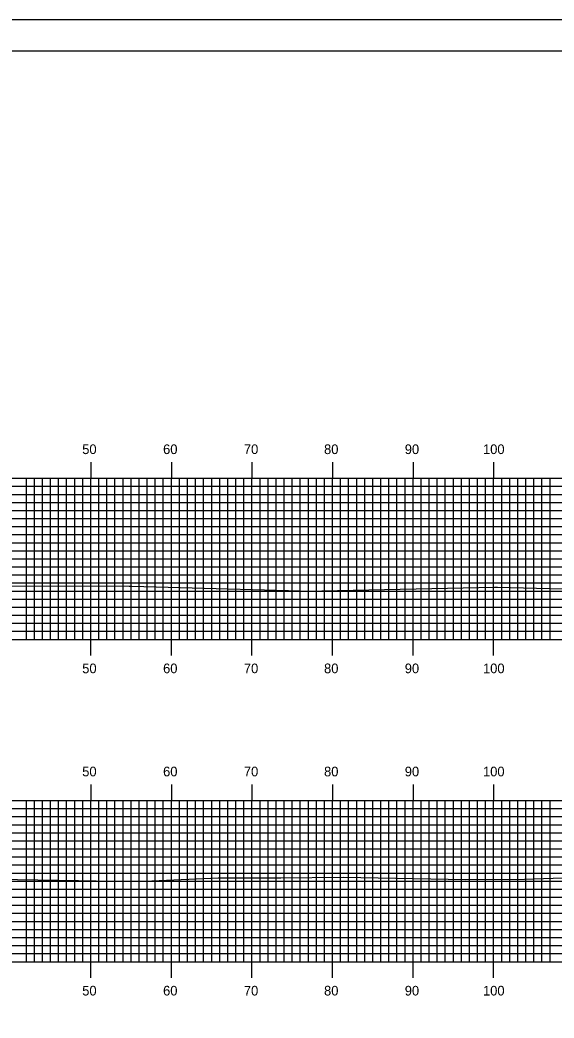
# Model space of a CAD drawing. Extents: x 1777925 to 1778268, y 442591 to 442811.
# Drawn here: x 1778132 to 1778198.3, y 442686.7 to 442810.5 of the extents above; entities that cross this region are included whole.
import ezdxf

# ---------------------------------------------------------------- set-up
doc = ezdxf.new("R2010")
doc.units = 0
for name, color, linetype in [('BORDER', 7, 'Continuous'), ('H_V ANNOTATION', 7, 'Continuous'), ('MAJOR', 7, 'Continuous'), ('MINOR', 7, 'Continuous'), ('PLOT BOUNDARY', 7, 'Continuous'), ('S_Roadway_Centerline', 7, 'Continuous')]:
    doc.layers.add(name, color=color, linetype=linetype)

msp = doc.modelspace()

# ---------------------------------------------------------------- linework, layer by layer
at = {"layer": 'BORDER'}
msp.add_lwpolyline([(1777941.19, 442596.67), (1778261.19, 442596.67), (1778261.19, 442806.67), (1777941.19, 442806.67)], close=True, dxfattribs=at)
at = {"layer": 'MAJOR'}
for p, q in [((1778140.79, 442755.67), (1778140.79, 442753.67)), ((1778150.79, 442755.67), (1778150.79, 442753.67)), ((1778160.79, 442755.67), (1778160.79, 442753.67)), ((1778170.79, 442755.67), (1778170.79, 442753.67)), ((1778180.79, 442755.67), (1778180.79, 442753.67)), ((1778190.79, 442755.67), (1778190.79, 442753.67)), ((1777950.79, 442753.67), (1778230.79, 442753.67)), ((1777950.79, 442753.67), (1778230.79, 442753.67)), ((1778140.79, 442733.67), (1778140.79, 442753.67)), ((1778150.79, 442733.67), (1778150.79, 442753.67)), ((1778160.79, 442733.67), (1778160.79, 442753.67)), ((1778170.79, 442733.67), (1778170.79, 442753.67)), ((1778180.79, 442733.67), (1778180.79, 442753.67)), ((1778190.79, 442733.67), (1778190.79, 442753.67)), ((1777950.79, 442748.67), (1778230.79, 442748.67)), ((1777950.79, 442743.67), (1778230.79, 442743.67)), ((1777950.79, 442738.67), (1778230.79, 442738.67)), ((1777950.79, 442733.67), (1778230.79, 442733.67)), ((1777950.79, 442733.67), (1778230.79, 442733.67)), ((1778140.79, 442731.66), (1778140.79, 442733.67)), ((1778150.79, 442731.66), (1778150.79, 442733.67)), ((1778160.79, 442731.66), (1778160.79, 442733.67)), ((1778170.79, 442731.66), (1778170.79, 442733.67)), ((1778180.79, 442731.66), (1778180.79, 442733.67)), ((1778190.79, 442731.66), (1778190.79, 442733.67)), ((1778140.79, 442715.67), (1778140.79, 442713.67)), ((1778150.79, 442715.67), (1778150.79, 442713.67)), ((1778160.79, 442715.67), (1778160.79, 442713.67)), ((1778170.79, 442715.67), (1778170.79, 442713.67)), ((1778180.79, 442715.67), (1778180.79, 442713.67)), ((1778190.79, 442715.67), (1778190.79, 442713.67)), ((1777950.79, 442713.67), (1778230.79, 442713.67)), ((1777950.79, 442713.67), (1778230.79, 442713.67)), ((1778140.79, 442693.67), (1778140.79, 442713.67)), ((1778150.79, 442693.67), (1778150.79, 442713.67)), ((1778160.79, 442693.67), (1778160.79, 442713.67)), ((1778170.79, 442693.67), (1778170.79, 442713.67)), ((1778180.79, 442693.67), (1778180.79, 442713.67)), ((1778190.79, 442693.67), (1778190.79, 442713.67)), ((1777950.79, 442708.67), (1778230.79, 442708.67)), ((1777950.79, 442703.67), (1778230.79, 442703.67)), ((1777950.79, 442698.67), (1778230.79, 442698.67)), ((1777950.79, 442693.67), (1778230.79, 442693.67)), ((1777950.79, 442693.67), (1778230.79, 442693.67)), ((1778140.79, 442691.66), (1778140.79, 442693.67)), ((1778150.79, 442691.66), (1778150.79, 442693.67)), ((1778160.79, 442691.66), (1778160.79, 442693.67)), ((1778170.79, 442691.66), (1778170.79, 442693.67)), ((1778180.79, 442691.66), (1778180.79, 442693.67)), ((1778190.79, 442691.66), (1778190.79, 442693.67))]:
    msp.add_line(p, q, dxfattribs=at)
at = {"layer": 'MINOR'}
for p, q in [((1778132.79, 442733.67), (1778132.79, 442753.67)), ((1778133.79, 442733.67), (1778133.79, 442753.67)), ((1778134.79, 442733.67), (1778134.79, 442753.67)), ((1778135.79, 442733.67), (1778135.79, 442753.67)), ((1778136.79, 442733.67), (1778136.79, 442753.67)), ((1778137.79, 442733.67), (1778137.79, 442753.67)), ((1778138.79, 442733.67), (1778138.79, 442753.67)), ((1778139.79, 442733.67), (1778139.79, 442753.67)), ((1778141.79, 442733.67), (1778141.79, 442753.67)), ((1778142.79, 442733.67), (1778142.79, 442753.67)), ((1778143.79, 442733.67), (1778143.79, 442753.67)), ((1778144.79, 442733.67), (1778144.79, 442753.67)), ((1778145.79, 442733.67), (1778145.79, 442753.67)), ((1778146.79, 442733.67), (1778146.79, 442753.67)), ((1778147.79, 442733.67), (1778147.79, 442753.67)), ((1778148.79, 442733.67), (1778148.79, 442753.67)), ((1778149.79, 442733.67), (1778149.79, 442753.67)), ((1778151.79, 442733.67), (1778151.79, 442753.67)), ((1778152.79, 442733.67), (1778152.79, 442753.67)), ((1778153.79, 442733.67), (1778153.79, 442753.67)), ((1778154.79, 442733.67), (1778154.79, 442753.67)), ((1778155.79, 442733.67), (1778155.79, 442753.67)), ((1778156.79, 442733.67), (1778156.79, 442753.67)), ((1778157.79, 442733.67), (1778157.79, 442753.67)), ((1778158.79, 442733.67), (1778158.79, 442753.67)), ((1778159.79, 442733.67), (1778159.79, 442753.67)), ((1778161.79, 442733.67), (1778161.79, 442753.67)), ((1778162.79, 442733.67), (1778162.79, 442753.67)), ((1778163.79, 442733.67), (1778163.79, 442753.67)), ((1778164.79, 442733.67), (1778164.79, 442753.67)), ((1778165.79, 442733.67), (1778165.79, 442753.67)), ((1778166.79, 442733.67), (1778166.79, 442753.67)), ((1778167.79, 442733.67), (1778167.79, 442753.67)), ((1778168.79, 442733.67), (1778168.79, 442753.67)), ((1778169.79, 442733.67), (1778169.79, 442753.67)), ((1778171.79, 442733.67), (1778171.79, 442753.67)), ((1778172.79, 442733.67), (1778172.79, 442753.67)), ((1778173.79, 442733.67), (1778173.79, 442753.67)), ((1778174.79, 442733.67), (1778174.79, 442753.67)), ((1778175.79, 442733.67), (1778175.79, 442753.67)), ((1778176.79, 442733.67), (1778176.79, 442753.67)), ((1778177.79, 442733.67), (1778177.79, 442753.67)), ((1778178.79, 442733.67), (1778178.79, 442753.67)), ((1778179.79, 442733.67), (1778179.79, 442753.67)), ((1778181.79, 442733.67), (1778181.79, 442753.67)), ((1778182.79, 442733.67), (1778182.79, 442753.67)), ((1778183.79, 442733.67), (1778183.79, 442753.67)), ((1778184.79, 442733.67), (1778184.79, 442753.67)), ((1778185.79, 442733.67), (1778185.79, 442753.67)), ((1778186.79, 442733.67), (1778186.79, 442753.67)), ((1778187.79, 442733.67), (1778187.79, 442753.67)), ((1778188.79, 442733.67), (1778188.79, 442753.67)), ((1778189.79, 442733.67), (1778189.79, 442753.67)), ((1778191.79, 442733.67), (1778191.79, 442753.67)), ((1778192.79, 442733.67), (1778192.79, 442753.67)), ((1778193.79, 442733.67), (1778193.79, 442753.67)), ((1778194.79, 442733.67), (1778194.79, 442753.67)), ((1778195.79, 442733.67), (1778195.79, 442753.67)), ((1778196.79, 442733.67), (1778196.79, 442753.67)), ((1778197.79, 442733.67), (1778197.79, 442753.67)), ((1777950.79, 442752.67), (1778230.79, 442752.67)), ((1777950.79, 442751.67), (1778230.79, 442751.67)), ((1777950.79, 442750.67), (1778230.79, 442750.67)), ((1777950.79, 442749.67), (1778230.79, 442749.67)), ((1777950.79, 442747.67), (1778230.79, 442747.67)), ((1777950.79, 442746.67), (1778230.79, 442746.67)), ((1777950.79, 442745.67), (1778230.79, 442745.67)), ((1777950.79, 442744.67), (1778230.79, 442744.67)), ((1777950.79, 442742.67), (1778230.79, 442742.67)), ((1777950.79, 442741.67), (1778230.79, 442741.67)), ((1777950.79, 442740.67), (1778230.79, 442740.67)), ((1777950.79, 442739.67), (1778230.79, 442739.67)), ((1777950.79, 442737.67), (1778230.79, 442737.67)), ((1777950.79, 442736.67), (1778230.79, 442736.67)), ((1777950.79, 442735.67), (1778230.79, 442735.67)), ((1777950.79, 442734.67), (1778230.79, 442734.67)), ((1778132.79, 442693.67), (1778132.79, 442713.67)), ((1778133.79, 442693.67), (1778133.79, 442713.67)), ((1778134.79, 442693.67), (1778134.79, 442713.67)), ((1778135.79, 442693.67), (1778135.79, 442713.67)), ((1778136.79, 442693.67), (1778136.79, 442713.67)), ((1778137.79, 442693.67), (1778137.79, 442713.67)), ((1778138.79, 442693.67), (1778138.79, 442713.67)), ((1778139.79, 442693.67), (1778139.79, 442713.67)), ((1778141.79, 442693.67), (1778141.79, 442713.67)), ((1778142.79, 442693.67), (1778142.79, 442713.67)), ((1778143.79, 442693.67), (1778143.79, 442713.67)), ((1778144.79, 442693.67), (1778144.79, 442713.67)), ((1778145.79, 442693.67), (1778145.79, 442713.67)), ((1778146.79, 442693.67), (1778146.79, 442713.67)), ((1778147.79, 442693.67), (1778147.79, 442713.67)), ((1778148.79, 442693.67), (1778148.79, 442713.67)), ((1778149.79, 442693.67), (1778149.79, 442713.67)), ((1778151.79, 442693.67), (1778151.79, 442713.67)), ((1778152.79, 442693.67), (1778152.79, 442713.67)), ((1778153.79, 442693.67), (1778153.79, 442713.67)), ((1778154.79, 442693.67), (1778154.79, 442713.67)), ((1778155.79, 442693.67), (1778155.79, 442713.67)), ((1778156.79, 442693.67), (1778156.79, 442713.67)), ((1778157.79, 442693.67), (1778157.79, 442713.67)), ((1778158.79, 442693.67), (1778158.79, 442713.67)), ((1778159.79, 442693.67), (1778159.79, 442713.67)), ((1778161.79, 442693.67), (1778161.79, 442713.67)), ((1778162.79, 442693.67), (1778162.79, 442713.67)), ((1778163.79, 442693.67), (1778163.79, 442713.67)), ((1778164.79, 442693.67), (1778164.79, 442713.67)), ((1778165.79, 442693.67), (1778165.79, 442713.67)), ((1778166.79, 442693.67), (1778166.79, 442713.67)), ((1778167.79, 442693.67), (1778167.79, 442713.67)), ((1778168.79, 442693.67), (1778168.79, 442713.67)), ((1778169.79, 442693.67), (1778169.79, 442713.67)), ((1778171.79, 442693.67), (1778171.79, 442713.67)), ((1778172.79, 442693.67), (1778172.79, 442713.67)), ((1778173.79, 442693.67), (1778173.79, 442713.67)), ((1778174.79, 442693.67), (1778174.79, 442713.67)), ((1778175.79, 442693.67), (1778175.79, 442713.67)), ((1778176.79, 442693.67), (1778176.79, 442713.67)), ((1778177.79, 442693.67), (1778177.79, 442713.67)), ((1778178.79, 442693.67), (1778178.79, 442713.67)), ((1778179.79, 442693.67), (1778179.79, 442713.67)), ((1778181.79, 442693.67), (1778181.79, 442713.67)), ((1778182.79, 442693.67), (1778182.79, 442713.67)), ((1778183.79, 442693.67), (1778183.79, 442713.67)), ((1778184.79, 442693.67), (1778184.79, 442713.67)), ((1778185.79, 442693.67), (1778185.79, 442713.67)), ((1778186.79, 442693.67), (1778186.79, 442713.67)), ((1778187.79, 442693.67), (1778187.79, 442713.67)), ((1778188.79, 442693.67), (1778188.79, 442713.67)), ((1778189.79, 442693.67), (1778189.79, 442713.67)), ((1778191.79, 442693.67), (1778191.79, 442713.67)), ((1778192.79, 442693.67), (1778192.79, 442713.67)), ((1778193.79, 442693.67), (1778193.79, 442713.67)), ((1778194.79, 442693.67), (1778194.79, 442713.67)), ((1778195.79, 442693.67), (1778195.79, 442713.67)), ((1778196.79, 442693.67), (1778196.79, 442713.67)), ((1778197.79, 442693.67), (1778197.79, 442713.67)), ((1777950.79, 442712.67), (1778230.79, 442712.67)), ((1777950.79, 442711.67), (1778230.79, 442711.67)), ((1777950.79, 442710.67), (1778230.79, 442710.67)), ((1777950.79, 442709.67), (1778230.79, 442709.67)), ((1777950.79, 442707.67), (1778230.79, 442707.67)), ((1777950.79, 442706.67), (1778230.79, 442706.67)), ((1777950.79, 442705.67), (1778230.79, 442705.67)), ((1777950.79, 442704.67), (1778230.79, 442704.67)), ((1777950.79, 442702.67), (1778230.79, 442702.67)), ((1777950.79, 442701.67), (1778230.79, 442701.67)), ((1777950.79, 442700.67), (1778230.79, 442700.67)), ((1777950.79, 442699.67), (1778230.79, 442699.67)), ((1777950.79, 442697.67), (1778230.79, 442697.67)), ((1777950.79, 442696.67), (1778230.79, 442696.67)), ((1777950.79, 442695.67), (1778230.79, 442695.67)), ((1777950.79, 442694.67), (1778230.79, 442694.67))]:
    msp.add_line(p, q, dxfattribs=at)
at = {"layer": 'PLOT BOUNDARY'}
msp.add_lwpolyline([(1777925, 442590.55), (1778265, 442590.55), (1778265, 442810.55), (1777925, 442810.55)], close=True, dxfattribs=at)
at = {"layer": 'S_Roadway_Centerline'}
for points in [[(1778123.36, 442740.3), (1778145.53, 442740.27), (1778145.73, 442740.27), (1778145.89, 442740.27), (1778150.39, 442740.14), (1778168.29, 442739.64), (1778169.47, 442739.68), (1778190.9, 442740.15), (1778191.09, 442740.14), (1778191.28, 442740.13), (1778204.21, 442739.83), (1778215.3, 442739.86), (1778216.68, 442739.84), (1778230.79, 442739.93)], [(1778126.6, 442703.95), (1778139.24, 442703.73), (1778143.63, 442703.67), (1778148.35, 442703.69), (1778156.61, 442704.07), (1778164.36, 442704.07), (1778172.11, 442704.17), (1778187.34, 442703.88), (1778194.63, 442703.89), (1778202.89, 442704.19), (1778212.57, 442703.88), (1778214.5, 442703.84), (1778215.91, 442703.84), (1778230.79, 442703.79)]]:
    msp.add_lwpolyline(points, dxfattribs=at)

# ---------------------------------------------------------------- texts
at = {"layer": 'H_V ANNOTATION'}
for s, p in [('50', (1778139.72, 442756.67)), ('60', (1778149.76, 442756.67)), ('70', (1778159.79, 442756.67)), ('80', (1778169.74, 442756.67)), ('90', (1778179.76, 442756.67)), ('100', (1778189.47, 442756.67)), ('50', (1778139.72, 442729.47)), ('60', (1778149.76, 442729.47)), ('70', (1778159.79, 442729.47)), ('80', (1778169.74, 442729.47)), ('90', (1778179.76, 442729.47)), ('100', (1778189.47, 442729.47)), ('50', (1778139.72, 442716.67)), ('60', (1778149.76, 442716.67)), ('70', (1778159.79, 442716.67)), ('80', (1778169.74, 442716.67)), ('90', (1778179.76, 442716.67)), ('100', (1778189.47, 442716.67)), ('50', (1778139.72, 442689.47)), ('60', (1778149.76, 442689.47)), ('70', (1778159.79, 442689.47)), ('80', (1778169.74, 442689.47)), ('90', (1778179.76, 442689.47)), ('100', (1778189.47, 442689.47))]:
    msp.add_text(s, height=1.2, dxfattribs=at).set_placement(p)

doc.saveas('drawing.dxf')
